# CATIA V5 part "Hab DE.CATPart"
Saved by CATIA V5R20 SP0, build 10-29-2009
Part number: Hab DE
Bounding box of the stored display mesh (mm): x -10 to 0, y 60.587 to 221.507, z -437.357 to 9.997
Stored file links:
  D:\Dropbox\IAO_2012\IAO_2012_766_vlaroche\vlaroche\vlaroche\IAO\A rendre\Hab DE.CATPart
  D:\Catia\IAO\A rendre\Assemblage.CATProduct
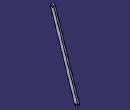
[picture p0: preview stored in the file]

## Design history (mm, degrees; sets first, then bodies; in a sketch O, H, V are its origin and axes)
Set1
  Point1: linked copy from another document
  Point2: linked copy from another document
Body1 (main body)
  Sketch1 on yz-plane, origin (0, 0, 0), H (0, 1, 0), V (0, 0, 1)
    construction line L1 (70.5772, 0) -> (211.517, -427.3593)
    point P1 (70.5772, 0)
    point P2 (211.517, -427.3593)
    line L2 (80.074, 3.132) -> (221.0139, -424.2273)
    line L3 (202.0201, -430.4913) -> (61.0803, -3.132)
    arc A1 centre (211.517, -427.3593) radius 10 from (221.0139, -424.2273) to (202.0201, -430.4913) cw
    arc A2 centre (70.5772, 0) radius 10 from (61.0803, -3.132) to (80.074, 3.132) cw
    reference projected point E1 (70.5772, 0) from Point1
    reference projected point E2 (211.517, -427.3593) from Point2
    circle A3 centre (211.517, -427.3593) radius 5
    circle A4 centre (70.5772, 0) radius 5
    distance L1 L2 = 10
    radius A3 = 5
    radius A4 = 5
    tangency: A1 L2, A2 L2, A1 L3, A2 L3
    coincidence: P1 E1, P2 E2
  Pad1: profile Sketch1, direction (-1, 0, 0), length 10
